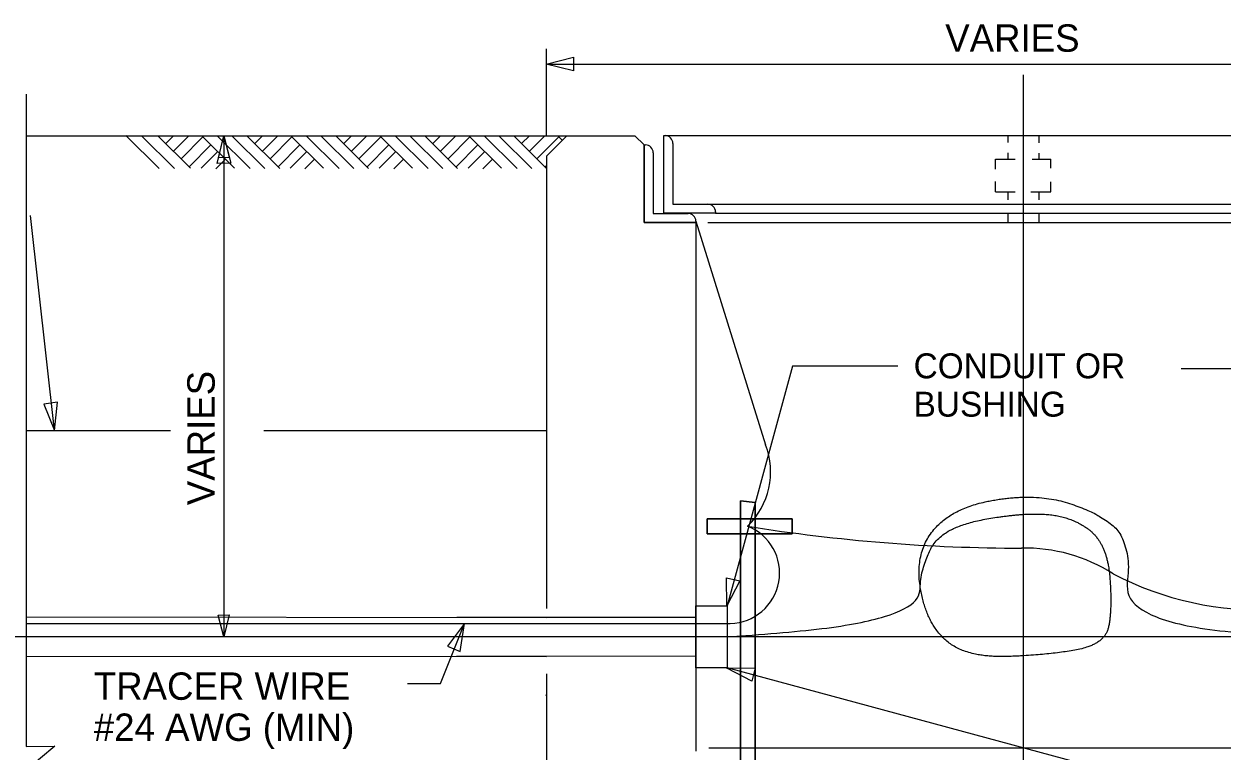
# Model space of a CAD drawing. Extents: x 1299104.8 to 1299141.6, y 239639.8 to 239661.8.
# Drawn here: x 1299110.98 to 1299116.23, y 239648.13 to 239651.31 of the extents above; entities that cross this region are included whole.
import ezdxf

# ---------------------------------------------------------------- set-up
doc = ezdxf.new("R2010")
doc.units = 0
doc.layers.add('DIM TXT', color=7, linetype='Continuous')

msp = doc.modelspace()

# ---------------------------------------------------------------- linework, layer by layer
at = {"layer": 'DIM TXT'}
for p, q in [((1299113.2733, 239650.8231), (1299113.2733, 239651.2043)), ((1299113.2794, 239651.1374), (1299117.4513, 239651.1374)), ((1299115.3623, 239651.0903), (1299115.3623, 239650.0162)), ((1299110.9938, 239651.0055), (1299110.9938, 239648.2261)), ((1299110.9933, 239650.8231), (1299111.9635, 239650.8231)), ((1299111.577, 239650.68), (1299111.431, 239650.8249)), ((1299111.6438, 239650.6802), (1299111.4999, 239650.8231)), ((1299111.7144, 239650.6805), (1299111.5707, 239650.8231)), ((1299111.6398, 239650.8231), (1299111.6055, 239650.7885)), ((1299111.7072, 239650.8231), (1299111.6398, 239650.7552)), ((1299111.7688, 239650.8181), (1299111.6726, 239650.7213)), ((1299111.9066, 239650.6812), (1299111.7638, 239650.8231)), ((1299111.975, 239650.68), (1299111.8308, 239650.8231)), ((1299111.8597, 239650.8231), (1299111.86, 239648.6265)), ((1299112.0399, 239650.68), (1299111.8957, 239650.8231)), ((1299112.1048, 239650.68), (1299111.9605, 239650.8231)), ((1299111.9635, 239650.8231), (1299113.3627, 239650.8231)), ((1299112.0296, 239650.8231), (1299111.9954, 239650.7885)), ((1299112.097, 239650.8231), (1299112.0297, 239650.7552)), ((1299112.1586, 239650.8181), (1299112.0625, 239650.7213)), ((1299112.2965, 239650.6812), (1299112.1536, 239650.8231)), ((1299112.3649, 239650.68), (1299112.2206, 239650.8231)), ((1299112.4297, 239650.68), (1299112.2855, 239650.8231)), ((1299112.4946, 239650.68), (1299112.3504, 239650.8231)), ((1299112.4195, 239650.8231), (1299112.3852, 239650.7885)), ((1299112.4869, 239650.8231), (1299112.4195, 239650.7552)), ((1299112.5485, 239650.8181), (1299112.4523, 239650.7213)), ((1299112.6863, 239650.6812), (1299112.5435, 239650.8231)), ((1299112.7547, 239650.68), (1299112.6105, 239650.8231)), ((1299112.8196, 239650.68), (1299112.6754, 239650.8231)), ((1299112.8844, 239650.68), (1299112.7402, 239650.8231)), ((1299112.8093, 239650.8231), (1299112.7751, 239650.7885)), ((1299112.8767, 239650.8231), (1299112.8094, 239650.7552)), ((1299112.9383, 239650.8181), (1299112.8422, 239650.7213)), ((1299113.0762, 239650.6812), (1299112.9333, 239650.8231)), ((1299113.1446, 239650.68), (1299113.0003, 239650.8231)), ((1299113.2094, 239650.68), (1299113.0652, 239650.8231)), ((1299113.2743, 239650.68), (1299113.1301, 239650.8231)), ((1299113.1992, 239650.8231), (1299113.1649, 239650.7885)), ((1299113.2666, 239650.8231), (1299113.1992, 239650.7552)), ((1299113.3282, 239650.8181), (1299113.232, 239650.7213)), ((1299113.2737, 239650.7341), (1299113.3627, 239650.8231)), ((1299113.343, 239650.8034), (1299113.3232, 239650.8231)), ((1299113.3627, 239650.8231), (1299113.6611, 239650.8231)), ((1299113.6611, 239650.8231), (1299113.7013, 239650.783)), ((1299113.7871, 239650.8237), (1299113.7932, 239650.8237)), ((1299113.7871, 239650.8237), (1299116.2016, 239650.8237)), ((1299115.2945, 239650.8237), (1299115.2945, 239650.7932)), ((1299115.4301, 239650.8237), (1299115.4301, 239650.7918)), ((1299116.2016, 239650.8237), (1299116.9375, 239650.8237)), ((1299111.8038, 239650.7834), (1299111.7083, 239650.6872)), ((1299111.8336, 239650.7538), (1299111.7611, 239650.6807)), ((1299112.1936, 239650.7834), (1299112.0982, 239650.6872)), ((1299112.2235, 239650.7538), (1299112.151, 239650.6807)), ((1299112.5835, 239650.7834), (1299112.488, 239650.6872)), ((1299112.6133, 239650.7538), (1299112.5408, 239650.6807)), ((1299112.9733, 239650.7834), (1299112.8779, 239650.6872)), ((1299113.0032, 239650.7538), (1299112.9307, 239650.6807)), ((1299113.7013, 239650.783), (1299113.7073, 239650.783)), ((1299113.7013, 239650.783), (1299113.7013, 239650.4425)), ((1299115.2945, 239650.7484), (1299115.2945, 239650.721)), ((1299115.4301, 239650.747), (1299115.4301, 239650.721)), ((1299111.8671, 239650.7205), (1299111.8258, 239650.6787)), ((1299112.257, 239650.7205), (1299112.2156, 239650.6787)), ((1299112.6468, 239650.7205), (1299112.6055, 239650.6787)), ((1299113.0366, 239650.7205), (1299112.9953, 239650.6787)), ((1299113.2733, 239650.6928), (1299113.2677, 239650.6872)), ((1299113.2733, 239650.7338), (1299113.2733, 239648.7515)), ((1299115.2413, 239650.6769), (1299115.2413, 239650.721)), ((1299115.2413, 239650.721), (1299115.3268, 239650.721)), ((1299115.401, 239650.721), (1299115.4833, 239650.721)), ((1299115.4833, 239650.6811), (1299115.4833, 239650.721)), ((1299115.2413, 239650.5774), (1299115.2413, 239650.6223)), ((1299115.4833, 239650.5774), (1299115.4833, 239650.6209)), ((1299115.2413, 239650.5774), (1299115.3268, 239650.5774)), ((1299115.2945, 239650.5774), (1299115.2945, 239650.5427)), ((1299115.3954, 239650.5774), (1299115.4833, 239650.5774)), ((1299115.4301, 239650.5774), (1299115.4301, 239650.5427)), ((1299113.9801, 239650.5233), (1299116.7445, 239650.5233)), ((1299114.0141, 239650.4892), (1299114.0141, 239650.4832)), ((1299114.0141, 239650.4832), (1299116.7105, 239650.4832)), ((1299114.0936, 239650.4832), (1299114.4883, 239650.4832)), ((1299114.6565, 239650.4832), (1299114.77, 239650.4832)), ((1299114.6943, 239650.4832), (1299114.9935, 239650.4832)), ((1299115.2945, 239650.4832), (1299115.2945, 239650.4436)), ((1299115.4301, 239650.4832), (1299115.4301, 239650.4436)), ((1299113.7013, 239650.4425), (1299113.9283, 239650.4425)), ((1299113.9282, 239650.4486), (1299114.2333, 239649.4687)), ((1299113.9283, 239650.4485), (1299113.9283, 239650.4425)), ((1299113.9283, 239650.4425), (1299113.9283, 239650.1488)), ((1299113.9801, 239650.4425), (1299114.2462, 239650.4425)), ((1299114.2462, 239650.4425), (1299116.4116, 239650.4425)), ((1299113.9283, 239650.1488), (1299113.9283, 239648.1261)), ((1299115.3623, 239650.0162), (1299115.3623, 239646.7778)), ((1299110.9933, 239649.5317), (1299111.6271, 239649.5317)), ((1299112.0358, 239649.5317), (1299113.2733, 239649.5317)), ((1299110.9938, 239648.7142), (1299113.2742, 239648.712)), ((1299113.9283, 239648.7117), (1299112.8803, 239648.712)), ((1299110.9938, 239648.6852), (1299114.0785, 239648.6856)), ((1299120.075, 239648.6265), (1299110.9016, 239648.6265)), ((1299110.9938, 239648.5414), (1299113.2733, 239648.5411)), ((1299113.9285, 239648.5411), (1299112.8805, 239648.5414)), ((1299113.9283, 239648.4903), (1299113.9283, 239648.4903)), ((1299113.2736, 239648.4652), (1299113.2736, 239647.5241)), ((1299110.9936, 239648.4082), (1299110.9942, 239648.1465)), ((1299113.2723, 239648.3706), (1299113.2692, 239648.3703)), ((1299110.9942, 239648.1465), (1299111.1201, 239648.1468)), ((1299111.1201, 239648.1468), (1299110.9944, 239648.0425)), ((1299113.9855, 239648.1407), (1299116.7437, 239648.1407))]:
    msp.add_line(p, q, dxfattribs=at)
for points in [[(1299113.392, 239651.1081), (1299113.2718, 239651.1374), (1299113.3916, 239651.1681)], [(1299111.8314, 239650.702), (1299111.8607, 239650.8221), (1299111.8914, 239650.7023)], [(1299111.8362, 239650.727), (1299111.8597, 239650.8231), (1299111.8842, 239650.7272)], [(1299111.0716, 239649.6463), (1299111.1183, 239649.5317), (1299111.131, 239649.6548)], [(1299114.1235, 239649.2232), (1299114.1882, 239649.215), (1299114.1882, 239646.4078), (1299114.1235, 239646.4078)], [(1299113.9778, 239649.1435), (1299114.3501, 239649.1435), (1299114.3501, 239649.0789), (1299113.9778, 239649.0789)], [(1299114.1213, 239648.872), (1299114.0639, 239648.7625), (1299114.0629, 239648.8861)], [(1299113.9283, 239648.4903), (1299113.9283, 239648.7627), (1299114.0645, 239648.7627), (1299114.0645, 239648.4903)], [(1299111.8835, 239648.7227), (1299111.86, 239648.6265), (1299111.8355, 239648.7224)], [(1299112.8952, 239648.5632), (1299112.9138, 239648.6854), (1299112.8398, 239648.5863)], [(1299114.1734, 239648.4327), (1299114.0639, 239648.4901), (1299114.1876, 239648.491)]]:
    msp.add_lwpolyline(points, close=True, dxfattribs=at)
for points in [[(1299114.0141, 239650.4832), (1299113.7871, 239650.4832), (1299113.7871, 239650.8237)], [(1299113.9283, 239650.4425), (1299113.7013, 239650.4425), (1299113.7013, 239650.783)], [(1299113.7414, 239650.7489), (1299113.7414, 239650.4826), (1299113.8942, 239650.4826)], [(1299113.8272, 239650.7896), (1299113.8272, 239650.5233), (1299113.9801, 239650.5233)], [(1299111.0116, 239650.4743), (1299111.1171, 239649.5317)], [(1299114.8134, 239649.8131), (1299114.3514, 239649.8131), (1299114.0645, 239648.7627)], [(1299116.0543, 239649.803), (1299116.325, 239649.803), (1299116.6602, 239648.7627)], [(1299114.1235, 239646.4078), (1299114.1882, 239646.4078), (1299114.1882, 239649.215), (1299114.1235, 239649.2232), (1299114.1235, 239646.4078)], [(1299113.9778, 239649.0789), (1299114.3501, 239649.0789), (1299114.3501, 239649.1435), (1299113.9778, 239649.1435), (1299113.9778, 239649.0789)], [(1299112.6644, 239648.4216), (1299112.8091, 239648.4216), (1299112.9138, 239648.6854)], [(1299117.6412, 239647.8902), (1299116.2853, 239647.8902), (1299114.0645, 239648.4903)]]:
    msp.add_lwpolyline(points, dxfattribs=at)
for centre, radius, start, end in [((1299113.7932, 239650.7896), 0.034, 0, 90), ((1299113.7073, 239650.7489), 0.034, 0, 90), ((1299113.8942, 239650.4486), 0.034, 0, 90), ((1299113.9801, 239650.4892), 0.034, 0, 90), ((1299113.9235, 239649.3497), 0.3319, 314.1726, 21.0119), ((1299114.074, 239648.9062), 0.2207, 271.1905, 68.5218), ((1299115.3553, 239656.5779), 7.5622, 260.86516, 269.99601), ((1299115.3695, 239648.2983), 0.7175, 57.4499, 91.1755), ((1299116.4044, 239650.1451), 1.4012, 242.4172, 272.7502)]:
    msp.add_arc(centre, radius, start, end, dxfattribs=at)
msp.add_open_spline([(1299114.0645, 239648.6265), (1299114.8919, 239648.6735), (1299114.9208, 239648.9681), (1299115.0306, 239649.1125), (1299115.3626, 239649.1723), (1299115.5799, 239649.153), (1299115.7302, 239649.0317), (1299115.7524, 239648.7447), (1299115.7186, 239648.5926), (1299115.47, 239648.5464), (1299115.1116, 239648.5348), (1299114.9381, 239648.685), (1299114.8861, 239648.9912), (1299115.048, 239649.1934), (1299115.4122, 239649.257), (1299115.6875, 239649.1745), (1299115.8342, 239649.0432), (1299115.8062, 239648.644), (1299116.6602, 239648.6265)], degree=2, dxfattribs=at)

# ---------------------------------------------------------------- texts
for s, height, p in [('VARIES', 0.12, (1299115.0205, 239651.1914)), ('CONDUIT OR', 0.10943, (1299114.882, 239649.7599)), ('BUSHING', 0.10943, (1299114.882, 239649.5919)), ('TRACER WIRE', 0.12, (1299111.2905, 239648.3507)), ('#24 AWG (MIN)', 0.12, (1299111.2905, 239648.1707))]:
    msp.add_text(s, height=height, dxfattribs=at).set_placement(p)
msp.add_text('VARIES', height=0.12, rotation=90, dxfattribs=at).set_placement((1299111.8202, 239649.2038))

doc.saveas('drawing.dxf')
